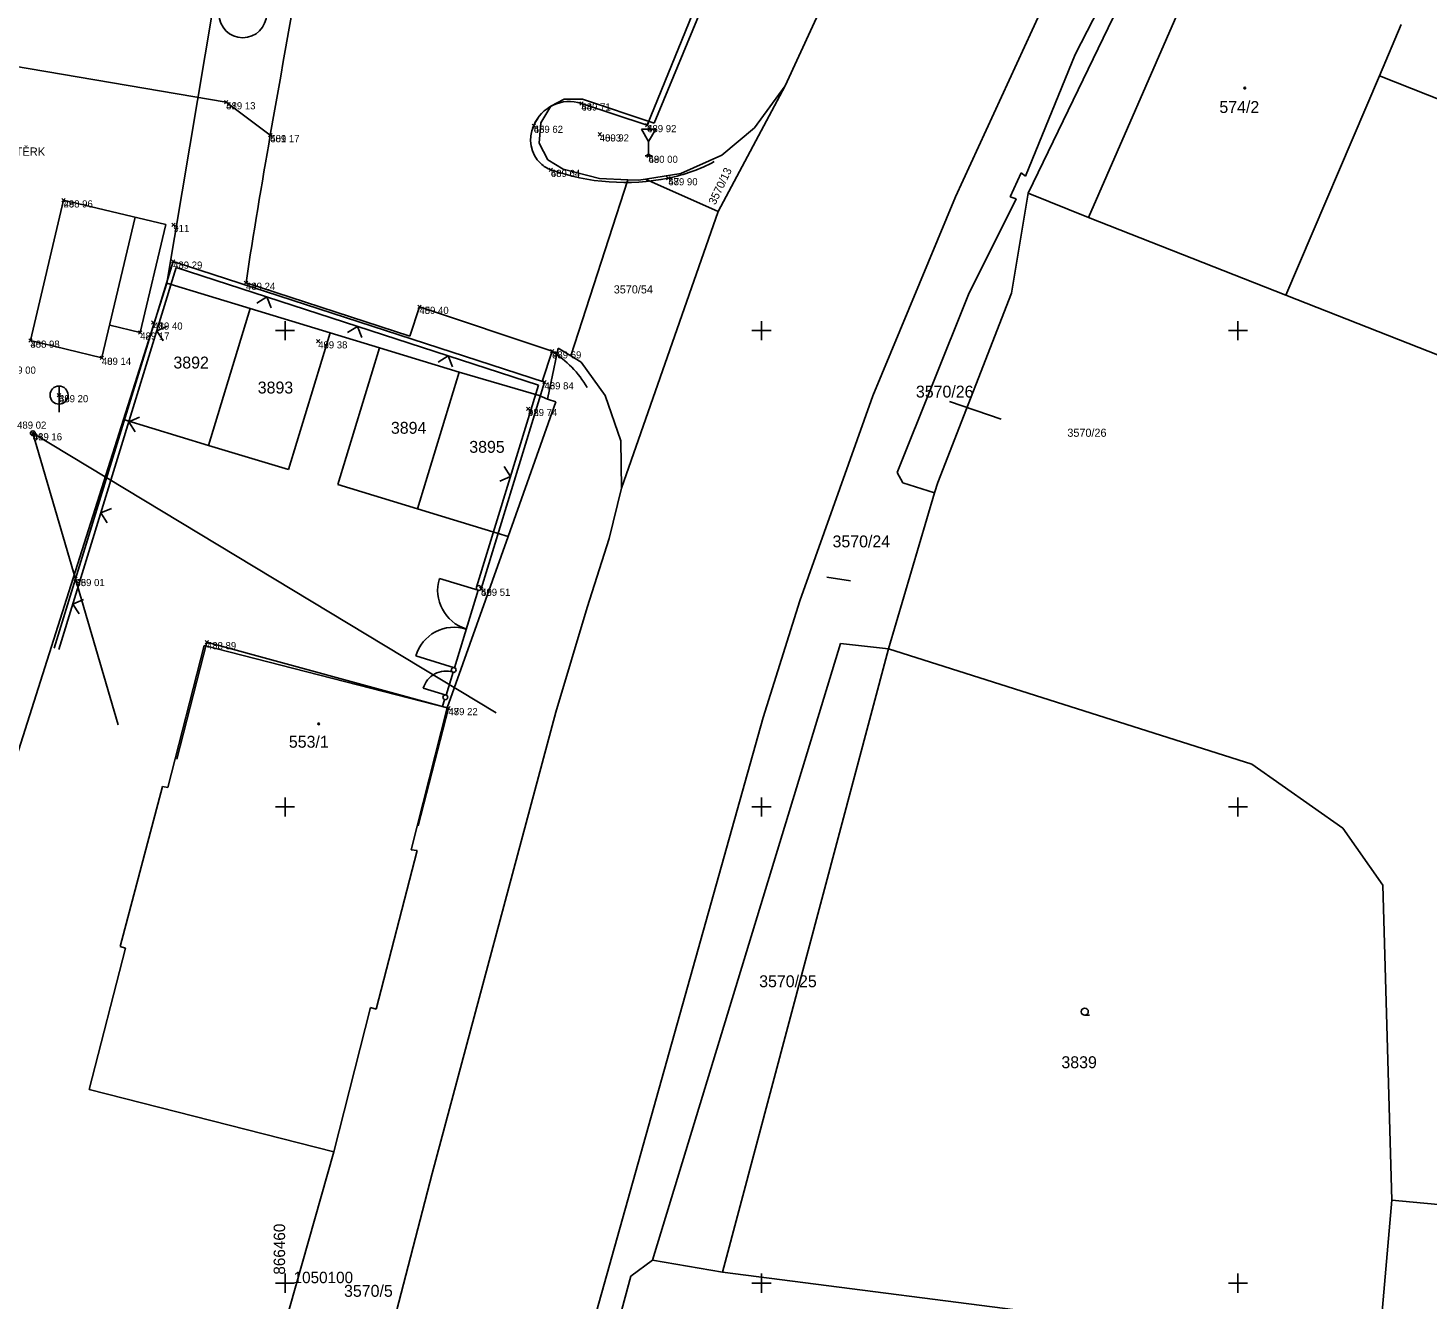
# Model space of a CAD drawing. Extents: x -866624 to -866276, y -1050208 to -1049940.
# Drawn here: x -866470.8 to -866412, y -1050100.7 to -1050047.3 of the extents above; entities that cross this region are included whole.
import ezdxf

# ---------------------------------------------------------------- set-up
doc = ezdxf.new("R2010")
doc.units = 0
for name, color, linetype in [('00_POMOCNÉ KCE', 7, 'Continuous'), ('_FORMATY', 7, 'Continuous'), ('bod-cislo', 7, 'Continuous'), ('bod-oznac', 7, 'Continuous'), ('bod-vyska', 7, 'Continuous'), ('BUDOVY', 7, 'Continuous'), ('CTV-SIT', 7, 'Continuous'), ('Default', 7, 'Continuous'), ('DOPR-ZAR', 7, 'Continuous'), ('EL-ZAR', 7, 'Continuous'), ('HRAN-LIN', 7, 'Continuous'), ('Hranice', 7, 'Continuous'), ('Hranice další', 7, 'Continuous'), ('Hranice-budov', 7, 'Continuous'), ('Parcela-pozemkova', 7, 'Continuous'), ('Parcela-stavebni', 7, 'Continuous'), ('Parcelni-cisla-pomocna', 7, 'Continuous'), ('PLOT-LIN', 7, 'Continuous'), ('POTR-ZAR', 7, 'Continuous'), ('SDEL-VED', 7, 'Continuous'), ('TEXT', 7, 'Continuous'), ('znacky-budov', 7, 'Continuous'), ('Znacky-kultury', 7, 'Continuous')]:
    doc.layers.add(name, color=color, linetype=linetype)

# ---------------------------------------------------------------- blocks, each defined once
blk = doc.blocks.new('p_zahr')
at = {"layer": 'Default'}
blk.add_line((0, -0.75), (0.99, -0.75), dxfattribs=at)
blk.add_circle((0, 0), 0.75, dxfattribs=at)
blk = doc.blocks.new('s_zdena')
at = {"layer": 'Default'}
blk.add_circle((0, 0), 0.175, dxfattribs=at)
for start, end in [(0, 180), (180, 0)]:
    blk.add_arc((0, 0), 0.0875, start, end, dxfattribs=at)
blk = doc.blocks.new('POINT_DISPLAY')
at = {"layer": 'Default'}
for p, q in [((-0.071, 0.071), (0.071, -0.071)), ((0.071, 0.071), (-0.071, -0.071))]:
    blk.add_line(p, q, dxfattribs=at)
blk = doc.blocks.new('200RS')
at = {"layer": 'POTR-ZAR'}
blk.add_line((0, -0.378), (0, 0.721), dxfattribs=at)
blk.add_circle((0, 0), 0.378, dxfattribs=at)
blk = doc.blocks.new('200DZ')
at = {"layer": 'DOPR-ZAR'}
for p, q in [((-0.149, 0), (0.149, 0)), ((0, -0.599), (0, 0)), ((-0.3, -1.119), (0, -0.599)), ((0, -1.119), (-0.3, -1.119)), ((0, -0.599), (0.3, -1.119)), ((0.3, -1.119), (0, -1.119))]:
    blk.add_line(p, q, dxfattribs=at)
blk = doc.blocks.new('pd')
at = {"layer": 'PLOT-LIN'}
for p in [(-0.319, 0.377), (0.319, 0.377)]:
    blk.add_line(p, (0, 0), dxfattribs=at)
blk = doc.blocks.new('CTVSIT')
at = {"layer": 'Default'}
for p, q in [((-2, 0), (2, 0)), ((0, 2), (0, -2))]:
    blk.add_line(p, q, dxfattribs=at)
blk = doc.blocks.new('vytyčení')
at = {"layer": '00_POMOCNÉ KCE'}
blk.add_circle((-866032.646, -1050070.404), 0.998, dxfattribs=at)
for centre, radius, start, end in [((-865314.028, -1020722.218), 29354.96, 268.567516, 268.6067194), ((-866020.999, -1049789.21), 279.372, 268.60672, 269.89538)]:
    blk.add_arc(centre, radius, start, end, dxfattribs=at)

msp = doc.modelspace()

# ---------------------------------------------------------------- linework, layer by layer
at = {"layer": '_FORMATY'}
msp.add_line((-866436.269, -1050070.508), (-866437.258, -1050070.359), dxfattribs=at)
at = {"layer": 'BUDOVY'}
for p, q in [((-866469.3, -1050054.53), (-866470.69, -1050060.42)), ((-866469.3, -1050054.53), (-866465.009, -1050055.543)), ((-866466.297, -1050055.239), (-866467.687, -1050061.129)), ((-866465.009, -1050055.543), (-866466.08, -1050060.08)), ((-866467.362, -1050059.772), (-866466.08, -1050060.08)), ((-866470.69, -1050060.42), (-866467.69, -1050061.14)), ((-866463.28, -1050073.08), (-866464.546, -1050078.003)), ((-866453.14, -1050075.85), (-866463.28, -1050073.08)), ((-866453.14, -1050075.85), (-866454.413, -1050080.801))]:
    msp.add_line(p, q, dxfattribs=at)
at = {"layer": 'EL-ZAR'}
for start, end in [(0, 180), (180, 0)]:
    msp.add_arc((-866470.59, -1050064.31), 0.1, start, end, dxfattribs=at)
at = {"layer": 'HRAN-LIN'}
for p, q in [((-866444.8, -1050051.37), (-866440.46, -1050040.72)), ((-866475.84, -1050048.14), (-866462.47, -1050050.41)), ((-866462.47, -1050050.41), (-866460.62, -1050051.79)), ((-866454.759, -1050060.228), (-866461.64, -1050057.99)), ((-866454.36, -1050059), (-866454.759, -1050060.228)), ((-866454.36, -1050059), (-866448.79, -1050060.87)), ((-866448.79, -1050060.87), (-866449.203, -1050062.14))]:
    msp.add_line(p, q, dxfattribs=at)
for points in [[(-866447.56, -1050050.46), (-866444.8, -1050051.37)], [(-866444.8, -1050051.37), (-866447.56, -1050050.46)]]:
    msp.add_lwpolyline(points, dxfattribs=at)
for centre, radius, start, end in [((-837550.449, -1055142.527), 29354.959, 169.9740709, 170.0132744), ((-866448.063, -1050051.987), 1.608, 71.75209, 158.59496), ((-866446.45, -1050052.867), 3.438, 148.01222, 154.7456), ((-866185.481, -1050100.239), 279.372, 170.01327, 171.30194), ((-866448.31, -1050051.99), 1.382, 154.7456, 226.33306), ((-866448.446, -1050052.132), 1.185, 226.33306, 250.5749), ((-866445.26, -1050046.845), 6.889, 281.30343, 298.35575), ((-866445.738, -1050044.454), 9.327, 250.5749, 281.30343), ((-866451.194, -1050064.678), 4.504, 30.56604, 57.73626)]:
    msp.add_arc(centre, radius, start, end, dxfattribs=at)
at = {"layer": 'Hranice'}
for p, q in [((-866444.5, -1050051.29), (-866440.12, -1050040.65)), ((-866423.91, -1050042.68), (-866426.83, -1050048.41)), ((-866428.8, -1050054.23), (-866423.99, -1050044.28)), ((-866421.31, -1050043.87), (-866426.27, -1050055.25)), ((-866431.86, -1050054.39), (-866427.77, -1050045.49)), ((-866437.25, -1050045.91), (-866439, -1050049.72)), ((-866464.96, -1050058.01), (-866463.03, -1050046.5)), ((-866413.14, -1050047.15), (-866414.06, -1050049.31)), ((-866426.83, -1050048.41), (-866428.91, -1050053.51)), ((-866414.06, -1050049.31), (-866417.99, -1050058.51)), ((-866441.82, -1050055), (-866439, -1050049.72)), ((-866439, -1050049.72), (-866440.29, -1050051.49)), ((-866449.27, -1050051.27), (-866448.85, -1050050.58)), ((-866448.85, -1050050.58), (-866448.28, -1050050.29)), ((-866448.28, -1050050.29), (-866447.51, -1050050.28)), ((-866447.51, -1050050.28), (-866444.5, -1050051.29)), ((-866449.34, -1050052.13), (-866449.27, -1050051.27)), ((-866440.29, -1050051.49), (-866441.66, -1050052.64)), ((-866448.97, -1050052.83), (-866449.34, -1050052.13)), ((-866448.33, -1050053.22), (-866448.97, -1050052.83)), ((-866441.66, -1050052.64), (-866443.39, -1050053.41)), ((-866446.8, -1050053.62), (-866448.33, -1050053.22)), ((-866448, -1050061.06), (-866445.61, -1050053.67)), ((-866445.61, -1050053.67), (-866446.8, -1050053.62)), ((-866445.17, -1050053.69), (-866445.61, -1050053.67)), ((-866444.87, -1050053.64), (-866445.17, -1050053.69)), ((-866443.39, -1050053.41), (-866444.87, -1050053.64)), ((-866441.82, -1050055), (-866444.87, -1050053.64)), ((-866429.1, -1050053.38), (-866429.56, -1050054.38)), ((-866428.91, -1050053.51), (-866429.1, -1050053.38)), ((-866428.8, -1050054.23), (-866429.5, -1050058.43)), ((-866426.27, -1050055.25), (-866428.8, -1050054.23)), ((-866431.86, -1050054.39), (-866435.32, -1050062.74)), ((-866429.31, -1050054.47), (-866431.31, -1050058.48)), ((-866429.56, -1050054.38), (-866429.31, -1050054.47)), ((-866445.88, -1050066.62), (-866441.82, -1050055)), ((-866426.27, -1050055.25), (-866417.99, -1050058.51)), ((-866466.78, -1050063.73), (-866464.96, -1050058.01)), ((-866464.96, -1050058.01), (-866461.46, -1050059.08)), ((-866429.5, -1050058.43), (-866432.6, -1050066.38)), ((-866431.31, -1050058.48), (-866434.3, -1050065.96)), ((-866417.99, -1050058.51), (-866410.39, -1050061.51)), ((-866463.21, -1050064.82), (-866461.46, -1050059.08)), ((-866461.46, -1050059.08), (-866458.11, -1050060.1)), ((-866458.11, -1050060.1), (-866459.86, -1050065.84)), ((-866458.11, -1050060.1), (-866456.04, -1050060.73)), ((-866457.79, -1050066.47), (-866456.04, -1050060.73)), ((-866456.04, -1050060.73), (-866452.69, -1050061.75)), ((-866448.83, -1050062.14), (-866448.53, -1050060.74)), ((-866448, -1050061.06), (-866448.53, -1050060.74)), ((-866447.57, -1050061.32), (-866448, -1050061.06)), ((-866446.56, -1050062.73), (-866447.57, -1050061.32)), ((-866452.69, -1050061.75), (-866454.44, -1050067.49)), ((-866452.69, -1050061.75), (-866449.33, -1050062.72)), ((-866448.99, -1050062.88), (-866448.83, -1050062.14)), ((-866450.64, -1050068.65), (-866448.63, -1050062.99)), ((-866449.33, -1050062.72), (-866448.99, -1050062.88)), ((-866448.63, -1050062.99), (-866448.99, -1050062.88)), ((-866445.91, -1050064.63), (-866446.56, -1050062.73)), ((-866435.32, -1050062.74), (-866438.39, -1050071.35)), ((-866466.78, -1050063.73), (-866476.6, -1050094.64)), ((-866463.21, -1050064.82), (-866466.78, -1050063.73)), ((-866459.86, -1050065.84), (-866463.21, -1050064.82)), ((-866445.88, -1050066.62), (-866445.91, -1050064.63)), ((-866434.3, -1050065.96), (-866434.06, -1050066.4)), ((-866454.44, -1050067.49), (-866457.79, -1050066.47)), ((-866446.39, -1050068.73), (-866445.88, -1050066.62)), ((-866434.06, -1050066.4), (-866432.73, -1050066.82)), ((-866432.6, -1050066.38), (-866432.73, -1050066.82)), ((-866432.73, -1050066.82), (-866434.67, -1050073.37)), ((-866451.1, -1050068.51), (-866454.44, -1050067.49)), ((-866450.64, -1050068.65), (-866453.19, -1050075.84)), ((-866450.64, -1050068.65), (-866451.1, -1050068.51)), ((-866447.32, -1050071.63), (-866446.39, -1050068.73)), ((-866438.39, -1050071.35), (-866439.93, -1050076.25)), ((-866448.64, -1050076.02), (-866447.32, -1050071.63)), ((-866436.69, -1050073.14), (-866444.57, -1050099.03)), ((-866434.67, -1050073.37), (-866436.69, -1050073.14)), ((-866441.63, -1050099.54), (-866434.67, -1050073.37)), ((-866419.42, -1050078.21), (-866434.67, -1050073.37)), ((-866453.19, -1050075.84), (-866454.71, -1050081.8)), ((-866453.82, -1050095.39), (-866448.64, -1050076.02)), ((-866439.93, -1050076.25), (-866449.97, -1050112.04)), ((-866415.59, -1050080.89), (-866419.42, -1050078.21)), ((-866413.91, -1050083.29), (-866415.59, -1050080.89)), ((-866456.17, -1050088.49), (-866454.46, -1050081.83)), ((-866454.71, -1050081.8), (-866454.46, -1050081.83)), ((-866413.91, -1050083.29), (-866413.54, -1050096.51)), ((-866456.41, -1050088.43), (-866457.96, -1050094.49)), ((-866456.41, -1050088.43), (-866456.17, -1050088.49)), ((-866457.96, -1050094.49), (-866463.4, -1050113.74)), ((-866458.78, -1050114.45), (-866453.82, -1050095.39)), ((-866413.54, -1050096.51), (-866414.11, -1050103.03)), ((-866444.57, -1050099.03), (-866445.48, -1050099.71)), ((-866444.57, -1050099.03), (-866441.63, -1050099.54)), ((-866426.4, -1050101.5), (-866441.63, -1050099.54)), ((-866445.48, -1050099.71), (-866447.75, -1050107.96))]:
    msp.add_line(p, q, dxfattribs=at)
at = {"layer": 'Hranice další'}
for p, q in [((-866406.73, -1050052.2), (-866414.06, -1050049.31)), ((-866464.92, -1050079.19), (-866463.4, -1050073.23)), ((-866453.19, -1050075.84), (-866463.4, -1050073.23)), ((-866466.92, -1050085.87), (-866465.15, -1050079.14)), ((-866464.92, -1050079.19), (-866465.15, -1050079.14)), ((-866466.7, -1050085.93), (-866468.22, -1050091.87)), ((-866466.7, -1050085.93), (-866466.92, -1050085.87)), ((-866457.96, -1050094.49), (-866468.22, -1050091.87)), ((-866399.34, -1050097.9), (-866413.54, -1050096.51))]:
    msp.add_line(p, q, dxfattribs=at)
at = {"layer": 'Hranice-budov'}
for p, q in [((-866421.31, -1050043.87), (-866426.27, -1050055.25)), ((-866413.14, -1050047.15), (-866414.06, -1050049.31)), ((-866414.06, -1050049.31), (-866417.99, -1050058.51)), ((-866426.27, -1050055.25), (-866417.99, -1050058.51)), ((-866464.92, -1050079.19), (-866463.4, -1050073.23)), ((-866453.19, -1050075.84), (-866463.4, -1050073.23)), ((-866453.19, -1050075.84), (-866454.71, -1050081.8)), ((-866466.92, -1050085.87), (-866465.15, -1050079.14)), ((-866464.92, -1050079.19), (-866465.15, -1050079.14)), ((-866456.17, -1050088.49), (-866454.46, -1050081.83)), ((-866454.71, -1050081.8), (-866454.46, -1050081.83)), ((-866466.7, -1050085.93), (-866468.22, -1050091.87)), ((-866466.7, -1050085.93), (-866466.92, -1050085.87)), ((-866456.41, -1050088.43), (-866457.96, -1050094.49)), ((-866456.41, -1050088.43), (-866456.17, -1050088.49)), ((-866457.96, -1050094.49), (-866468.22, -1050091.87))]:
    msp.add_line(p, q, dxfattribs=at)
at = {"layer": 'Parcelni-cisla-pomocna'}
msp.add_line((-866429.94, -1050063.72), (-866432.11, -1050062.98), dxfattribs=at)
at = {"layer": 'PLOT-LIN'}
for p, q in [((-866464.7, -1050057.1), (-866469.693, -1050073.335)), ((-866449.11, -1050062.17), (-866464.7, -1050057.1)), ((-866464.569, -1050057.353), (-866469.502, -1050073.393)), ((-866449.359, -1050062.299), (-866464.569, -1050057.353)), ((-866449.359, -1050062.299), (-866451.961, -1050070.781)), ((-866449.11, -1050062.17), (-866451.77, -1050070.84)), ((-866451.895, -1050070.906), (-866453.52, -1050070.408)), ((-866451.895, -1050070.906), (-866452.892, -1050074.156)), ((-866452.892, -1050074.156), (-866454.516, -1050073.657)), ((-866452.95, -1050074.347), (-866453.244, -1050075.303)), ((-866453.244, -1050075.303), (-866454.201, -1050075.01)), ((-866453.303, -1050075.495), (-866453.39, -1050075.779))]:
    msp.add_line(p, q, dxfattribs=at)
for centre in [(-866451.866, -1050070.811), (-866452.921, -1050074.251), (-866453.273, -1050075.399)]:
    msp.add_circle(centre, 0.1, dxfattribs=at)
for centre, radius, start, end in [((-866451.895, -1050070.906), 1.699, 162.94372, 252.94372), ((-866452.892, -1050074.156), 1.699, 72.94372, 162.94372), ((-866453.244, -1050075.303), 1.001, 72.94372, 162.94372)]:
    msp.add_arc(centre, radius, start, end, dxfattribs=at)
at = {"layer": 'SDEL-VED'}
for q in [(-866467.01, -1050076.55), (-866451.134, -1050076.057)]:
    msp.add_line((-866470.59, -1050064.31), q, dxfattribs=at)

# ---------------------------------------------------------------- block references
at = {"layer": '00_POMOCNÉ KCE', "rotation": -98.59344504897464}
msp.add_blockref('vytyčení', (42415.469, -2063260.675), dxfattribs=at)
at = {"layer": 'bod-oznac'}
for p in [(-866462.47, -1050050.41), (-866447.56, -1050050.46), (-866449.56, -1050051.4), (-866444.8, -1050051.37), (-866460.62, -1050051.79), (-866446.79, -1050051.76), (-866444.74, -1050052.66), (-866448.84, -1050053.25), (-866443.91, -1050053.6), (-866469.3, -1050054.53), (-866464.69, -1050055.56), (-866464.7, -1050057.1), (-866461.64, -1050057.99), (-866454.36, -1050059), (-866465.53, -1050059.66), (-866466.08, -1050060.08), (-866470.69, -1050060.42), (-866458.61, -1050060.45), (-866448.79, -1050060.87), (-866467.69, -1050061.14), (-866449.11, -1050062.17), (-866469.49, -1050062.71), (-866449.8, -1050063.29), (-866470.59, -1050064.31), (-866468.8, -1050070.43), (-866451.77, -1050070.84), (-866463.28, -1050073.08), (-866453.14, -1050075.85)]:
    msp.add_blockref('POINT_DISPLAY', p, dxfattribs=at)
at = {"layer": 'CTV-SIT', "xscale": 0.19999999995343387, "yscale": 0.19999999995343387}
for p in [(-866460, -1050060), (-866440, -1050060), (-866420, -1050060), (-866460, -1050080), (-866440, -1050080), (-866420, -1050080), (-866460, -1050100), (-866440, -1050100), (-866420, -1050100)]:
    msp.add_blockref('CTVSIT', p, dxfattribs=at)
at = {"layer": 'DOPR-ZAR', "rotation": 179.99999999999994}
msp.add_blockref('200DZ', (-866444.74, -1050052.66), dxfattribs=at)
at = {"layer": 'PLOT-LIN'}
for p, rotation in [((-866460.765, -1050058.59), 161.98503586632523), ((-866465.386, -1050060.012), -107.0966879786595), ((-866456.961, -1050059.827), 161.98503586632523), ((-866453.157, -1050061.064), 161.98503586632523), ((-866466.562, -1050063.835), -107.0966879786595), ((-866467.738, -1050067.659), -107.0966879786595), ((-866468.914, -1050071.482), -107.0966879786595)]:
    msp.add_blockref('pd', p, dxfattribs=dict(at, rotation=rotation))
at = {"layer": 'PLOT-LIN', "yscale": -0.9999999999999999, "rotation": -107.05627921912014}
msp.add_blockref('pd', (-866450.532, -1050066.123), dxfattribs=at)
at = {"layer": 'POTR-ZAR', "rotation": 179.99999999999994}
msp.add_blockref('200RS', (-866469.49, -1050062.71), dxfattribs=at)
at = {"layer": 'znacky-budov', "xscale": 0.2, "yscale": 0.20000000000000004}
for p in [(-866419.71, -1050049.82), (-866458.59, -1050076.515)]:
    msp.add_blockref('s_zdena', p, dxfattribs=at)
at = {"layer": 'Znacky-kultury', "xscale": 0.2, "yscale": 0.20000000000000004}
msp.add_blockref('p_zahr', (-866426.43, -1050088.6), dxfattribs=at)

# ---------------------------------------------------------------- texts
at = {"layer": 'bod-cislo'}
for s, p in [('51', (-866462.47, -1050050.71)), ('64', (-866447.56, -1050050.76)), ('65', (-866449.56, -1050051.7)), ('63', (-866444.8, -1050051.67)), ('501', (-866460.62, -1050052.09)), ('4003', (-866446.79, -1050052.06)), ('68', (-866444.74, -1050052.96)), ('66', (-866448.84, -1050053.55)), ('67', (-866443.91, -1050053.9)), ('29', (-866469.3, -1050054.83)), ('911', (-866464.69, -1050055.86)), ('43', (-866464.7, -1050057.4)), ('44', (-866461.64, -1050058.29)), ('45', (-866454.36, -1050059.3)), ('42', (-866466.08, -1050060.38)), ('41', (-866465.53, -1050059.96)), ('30', (-866470.69, -1050060.72)), ('49', (-866458.61, -1050060.75)), ('40', (-866467.69, -1050061.44)), ('93', (-866448.79, -1050061.17)), ('46', (-866449.11, -1050062.47)), ('39', (-866469.49, -1050063.01)), ('92', (-866449.8, -1050063.59)), ('31', (-866470.59, -1050064.61)), ('36', (-866468.8, -1050070.73)), ('50', (-866451.77, -1050071.14)), ('48', (-866463.28, -1050073.38)), ('47', (-866453.14, -1050076.15))]:
    msp.add_text(s, height=0.3, dxfattribs=at).set_placement(p)
at = {"layer": 'bod-vyska'}
for s, p in [('489 13', (-866462.47, -1050050.71)), ('489 71', (-866447.56, -1050050.76)), ('489 62', (-866449.56, -1050051.7)), ('489 92', (-866444.8, -1050051.67)), ('489 17', (-866460.62, -1050052.09)), ('489 92', (-866446.79, -1050052.06)), ('490 00', (-866444.74, -1050052.96)), ('489 64', (-866448.84, -1050053.55)), ('489 90', (-866443.91, -1050053.9)), ('488 96', (-866469.3, -1050054.83)), ('489 29', (-866464.7, -1050057.4)), ('489 24', (-866461.64, -1050058.29)), ('489 40', (-866454.36, -1050059.3)), ('489 17', (-866466.08, -1050060.38)), ('489 40', (-866465.53, -1050059.96)), ('488 98', (-866470.69, -1050060.72)), ('489 38', (-866458.61, -1050060.75)), ('489 14', (-866467.69, -1050061.44)), ('489 69', (-866448.79, -1050061.17)), ('489 00', (-866471.69, -1050061.81)), ('489 84', (-866449.11, -1050062.47)), ('489 20', (-866469.49, -1050063.01)), ('489 74', (-866449.8, -1050063.59)), ('489 02', (-866471.25, -1050064.12)), ('489 16', (-866470.59, -1050064.61)), ('489 01', (-866468.8, -1050070.73)), ('489 51', (-866451.77, -1050071.14)), ('488 89', (-866463.28, -1050073.38)), ('489 22', (-866453.14, -1050076.15))]:
    msp.add_text(s, height=0.3, dxfattribs=at).set_placement(p)
at = {"layer": 'CTV-SIT'}
msp.add_text('  866460', height=0.48, rotation=90, dxfattribs=at).set_placement((-866460, -1050100))
msp.add_text('  1050100', height=0.48, dxfattribs=at).set_placement((-866460, -1050100))
at = {"layer": 'Parcela-pozemkova'}
for s, p in [('3892', (-866464.687, -1050061.593)), ('3893', (-866461.147, -1050062.643)), ('3570/26', (-866433.517, -1050062.813)), ('3894', (-866455.557, -1050064.333)), ('3895', (-866452.267, -1050065.133)), ('3570/24', (-866437.017, -1050069.103)), ('3570/25', (-866440.097, -1050087.573)), ('3839', (-866427.409, -1050090.973)), ('3570/5', (-866457.524, -1050100.573))]:
    msp.add_text(s, height=0.5, dxfattribs=at).set_placement(p)
at = {"layer": 'Parcela-stavebni'}
for s, p in [('574/2', (-866420.777, -1050050.862)), ('553/1', (-866459.841, -1050077.516))]:
    msp.add_text(s, height=0.5, dxfattribs=at).set_placement(p)
at = {"layer": 'Parcelni-cisla-pomocna'}
msp.add_text('3570/13', height=0.34, rotation=64.5723, dxfattribs=at).set_placement((-866441.939, -1050054.747))
for s, p in [('3570/54', (-866446.202, -1050058.441)), ('3570/26', (-866427.16, -1050064.46))]:
    msp.add_text(s, height=0.34, dxfattribs=at).set_placement(p)
at = {"layer": 'TEXT'}
msp.add_text('ŠTĚRK', height=0.35, dxfattribs=at).set_placement((-866471.631, -1050052.662))

doc.saveas('drawing.dxf')
